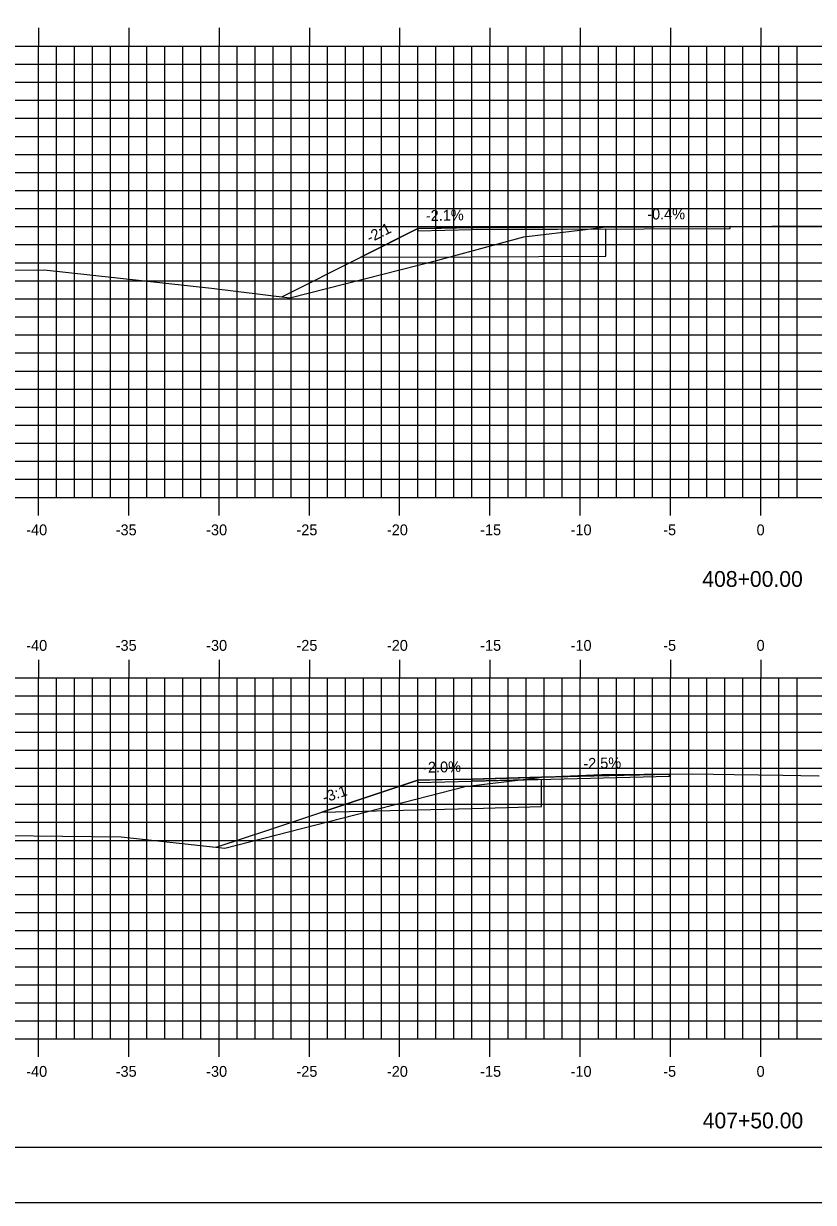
# Model space of a CAD drawing. Extents: x 1168600 to 1177589, y 610178 to 611246.
# Drawn here: x 1171818.2 to 1171862, y 610900.5 to 610965.8 of the extents above; entities that cross this region are included whole.
import ezdxf

# ---------------------------------------------------------------- set-up
doc = ezdxf.new("R2010")
doc.units = 0
for name, color, linetype in [('_Construction', 7, 'Continuous'), ('_Station Equation', 7, 'Continuous'), ('ANNOTATION', 7, 'Continuous'), ('D_Roadway_Edge_TW', 7, 'Continuous'), ('D_Roadway_SubGrade', 7, 'Continuous'), ('D_Slope_Direction', 7, 'Continuous'), ('D_Text_Standard', 7, 'Continuous'), ('H_V ANNOTATION', 7, 'Continuous'), ('MAJOR', 7, 'Continuous'), ('MATCH LINES', 7, 'Continuous'), ('MINOR', 7, 'Continuous')]:
    doc.layers.add(name, color=color, linetype=linetype)

msp = doc.modelspace()

# ---------------------------------------------------------------- linework, layer by layer
at = {"layer": '_Construction'}
msp.add_line((1171784.045, 610903.596), (1171944.045, 610903.596), dxfattribs=at)
msp.add_lwpolyline([(1171775.952, 610900.537), (1171945.952, 610900.537), (1171945.952, 611010.537), (1171775.952, 611010.537)], close=True, dxfattribs=at)
at = {"layer": '_Station Equation'}
for points in [[(1171789.045, 610951.753), (1171796.372, 610951.968), (1171801.834, 610952.028), (1171819.364, 610952.207), (1171828.631, 610951.19), (1171832.957, 610950.654), (1171841.161, 610952.733), (1171845.923, 610954.036), (1171849.324, 610954.437), (1171850.462, 610954.581), (1171859.649, 610954.616), (1171864.065, 610954.632)], [(1171789.045, 610951.753), (1171796.372, 610951.968), (1171801.834, 610952.028), (1171819.364, 610952.207), (1171828.631, 610951.19), (1171832.957, 610950.654), (1171841.161, 610952.733), (1171845.923, 610954.036), (1171849.324, 610954.437), (1171850.462, 610954.581), (1171859.65, 610954.616), (1171864.065, 610954.632)], [(1171789.045, 610920.994), (1171795.223, 610920.863), (1171804.231, 610921.006), (1171823.634, 610920.786), (1171829.366, 610920.156), (1171837.933, 610922.363), (1171842.674, 610923.573), (1171846.665, 610924.058), (1171846.891, 610924.088), (1171848.054, 610924.142), (1171850.234, 610924.245), (1171852.586, 610924.259), (1171855.246, 610924.275), (1171857.567, 610924.244), (1171860.258, 610924.209), (1171862.259, 610924.171)], [(1171789.045, 610920.994), (1171795.223, 610920.863), (1171804.231, 610921.006), (1171823.634, 610920.786), (1171829.366, 610920.156), (1171837.933, 610922.363), (1171842.674, 610923.573), (1171846.664, 610924.058), (1171846.891, 610924.088), (1171848.055, 610924.142), (1171850.234, 610924.245), (1171852.585, 610924.259), (1171855.246, 610924.275), (1171857.567, 610924.244), (1171860.258, 610924.209), (1171862.26, 610924.171)]]:
    msp.add_lwpolyline(points, dxfattribs=at)
at = {"layer": 'D_Roadway_Edge_TW'}
for points in [[(1171857.338, 610954.607), (1171850.462, 610954.581), (1171843.044, 610954.553), (1171840.052, 610954.491), (1171840.052, 610954.366), (1171843.044, 610954.428), (1171857.338, 610954.482)], [(1171857.338, 610954.607), (1171850.462, 610954.581), (1171843.044, 610954.553), (1171840.052, 610954.491), (1171840.052, 610954.366), (1171843.044, 610954.428), (1171857.338, 610954.482)], [(1171857.338, 610954.607), (1171850.462, 610954.581), (1171843.044, 610954.553), (1171843.044, 610954.428), (1171857.338, 610954.482), (1171857.338, 610954.607)], [(1171857.338, 610954.607), (1171850.462, 610954.581), (1171843.044, 610954.553), (1171843.044, 610954.428), (1171857.338, 610954.482), (1171857.338, 610954.607)], [(1171853.976, 610924.268), (1171846.891, 610924.09), (1171843.045, 610923.993), (1171840.05, 610923.932), (1171840.05, 610923.807), (1171843.045, 610923.868), (1171853.976, 610924.143)], [(1171853.976, 610924.268), (1171846.891, 610924.09), (1171843.045, 610923.993), (1171840.05, 610923.932), (1171840.05, 610923.807), (1171843.045, 610923.868), (1171853.976, 610924.143)]]:
    msp.add_lwpolyline(points, close=True, dxfattribs=at)
msp.add_lwpolyline([(1171853.976, 610924.268), (1171846.891, 610924.09), (1171843.045, 610923.993), (1171843.045, 610923.868), (1171853.976, 610924.143), (1171853.976, 610924.268)], dxfattribs=at)
msp.add_lwpolyline([(1171853.976, 610924.268), (1171846.891, 610924.09), (1171843.045, 610923.993), (1171843.045, 610923.868), (1171853.976, 610924.143), (1171853.976, 610924.268)], dxfattribs=at)
at = {"layer": 'D_Roadway_SubGrade'}
for points in [[(1171843.044, 610954.553), (1171840.052, 610954.491), (1171836.893, 610952.905), (1171843.044, 610952.928), (1171850.462, 610952.956), (1171850.462, 610954.456), (1171843.044, 610954.428)], [(1171843.044, 610954.553), (1171840.052, 610954.491), (1171836.893, 610952.905), (1171843.044, 610952.928), (1171850.462, 610952.956), (1171850.462, 610954.456), (1171843.044, 610954.428)], [(1171843.045, 610923.993), (1171840.05, 610923.932), (1171834.733, 610922.16), (1171843.045, 610922.368), (1171846.891, 610922.465), (1171846.891, 610923.965), (1171843.045, 610923.868)], [(1171843.045, 610923.993), (1171840.05, 610923.932), (1171834.733, 610922.16), (1171843.045, 610922.368), (1171846.891, 610922.465), (1171846.891, 610923.965), (1171843.045, 610923.868)]]:
    msp.add_lwpolyline(points, close=True, dxfattribs=at)
at = {"layer": 'D_Slope_Direction'}
for points in [[(1171843.044, 610954.553), (1171840.052, 610954.491)], [(1171843.044, 610954.553), (1171840.052, 610954.491)], [(1171843.045, 610923.993), (1171840.05, 610923.932)], [(1171843.045, 610923.993), (1171840.05, 610923.932)]]:
    msp.add_lwpolyline(points, dxfattribs=at)
at = {"layer": 'D_Text_Standard'}
for points in [[(1171832.518, 610950.709), (1171836.893, 610952.905), (1171838.113, 610953.517), (1171840.052, 610954.491), (1171841.355, 610954.518), (1171843.044, 610954.553), (1171846.989, 610954.568), (1171850.462, 610954.581), (1171853.126, 610954.591), (1171857.338, 610954.607)], [(1171828.883, 610920.21), (1171830.511, 610920.752), (1171831.687, 610921.144), (1171836.671, 610922.806), (1171840.05, 610923.932), (1171841.401, 610923.96), (1171843.045, 610923.993), (1171845.067, 610924.044), (1171846.891, 610924.09), (1171849.816, 610924.163), (1171853.976, 610924.268)]]:
    msp.add_lwpolyline(points, dxfattribs=at)
at = {"layer": 'MAJOR'}
for p, q in [((1171819.045, 610965.598), (1171819.045, 610964.596)), ((1171824.045, 610965.598), (1171824.045, 610964.596)), ((1171829.045, 610965.598), (1171829.045, 610964.596)), ((1171834.045, 610965.598), (1171834.045, 610964.596)), ((1171839.045, 610965.598), (1171839.045, 610964.596)), ((1171844.045, 610965.598), (1171844.045, 610964.596)), ((1171849.045, 610965.598), (1171849.045, 610964.596)), ((1171854.045, 610965.598), (1171854.045, 610964.596)), ((1171859.045, 610965.598), (1171859.045, 610964.596)), ((1171789.045, 610964.596), (1171929.045, 610964.596)), ((1171789.045, 610964.596), (1171929.045, 610964.596)), ((1171819.045, 610939.596), (1171819.045, 610964.596)), ((1171824.045, 610939.596), (1171824.045, 610964.596)), ((1171829.045, 610939.596), (1171829.045, 610964.596)), ((1171834.045, 610939.596), (1171834.045, 610964.596)), ((1171839.045, 610939.596), (1171839.045, 610964.596)), ((1171844.045, 610939.596), (1171844.045, 610964.596)), ((1171849.045, 610939.596), (1171849.045, 610964.596)), ((1171854.045, 610939.596), (1171854.045, 610964.596)), ((1171859.045, 610939.596), (1171859.045, 610964.596)), ((1171789.045, 610959.596), (1171929.045, 610959.596)), ((1171789.045, 610954.596), (1171929.045, 610954.596)), ((1171789.045, 610949.596), (1171929.045, 610949.596)), ((1171789.045, 610944.596), (1171929.045, 610944.596)), ((1171789.045, 610939.596), (1171929.045, 610939.596)), ((1171789.045, 610939.596), (1171929.045, 610939.596)), ((1171819.045, 610938.594), (1171819.045, 610939.596)), ((1171824.045, 610938.594), (1171824.045, 610939.596)), ((1171829.045, 610938.594), (1171829.045, 610939.596)), ((1171834.045, 610938.594), (1171834.045, 610939.596)), ((1171839.045, 610938.594), (1171839.045, 610939.596)), ((1171844.045, 610938.594), (1171844.045, 610939.596)), ((1171849.045, 610938.594), (1171849.045, 610939.596)), ((1171854.045, 610938.594), (1171854.045, 610939.596)), ((1171859.045, 610938.594), (1171859.045, 610939.596)), ((1171819.045, 610930.598), (1171819.045, 610929.596)), ((1171824.045, 610930.598), (1171824.045, 610929.596)), ((1171829.045, 610930.598), (1171829.045, 610929.596)), ((1171834.045, 610930.598), (1171834.045, 610929.596)), ((1171839.045, 610930.598), (1171839.045, 610929.596)), ((1171844.045, 610930.598), (1171844.045, 610929.596)), ((1171849.045, 610930.598), (1171849.045, 610929.596)), ((1171854.045, 610930.598), (1171854.045, 610929.596)), ((1171859.045, 610930.598), (1171859.045, 610929.596)), ((1171789.045, 610929.596), (1171929.045, 610929.596)), ((1171789.045, 610929.596), (1171929.045, 610929.596)), ((1171819.045, 610909.596), (1171819.045, 610929.596)), ((1171824.045, 610909.596), (1171824.045, 610929.596)), ((1171829.045, 610909.596), (1171829.045, 610929.596)), ((1171834.045, 610909.596), (1171834.045, 610929.596)), ((1171839.045, 610909.596), (1171839.045, 610929.596)), ((1171844.045, 610909.596), (1171844.045, 610929.596)), ((1171849.045, 610909.596), (1171849.045, 610929.596)), ((1171854.045, 610909.596), (1171854.045, 610929.596)), ((1171859.045, 610909.596), (1171859.045, 610929.596)), ((1171789.045, 610924.596), (1171929.045, 610924.596)), ((1171789.045, 610919.596), (1171929.045, 610919.596)), ((1171789.045, 610914.596), (1171929.045, 610914.596)), ((1171789.045, 610909.596), (1171929.045, 610909.596)), ((1171789.045, 610909.596), (1171929.045, 610909.596)), ((1171819.045, 610908.594), (1171819.045, 610909.596)), ((1171824.045, 610908.594), (1171824.045, 610909.596)), ((1171829.045, 610908.594), (1171829.045, 610909.596)), ((1171834.045, 610908.594), (1171834.045, 610909.596)), ((1171839.045, 610908.594), (1171839.045, 610909.596)), ((1171844.045, 610908.594), (1171844.045, 610909.596)), ((1171849.045, 610908.594), (1171849.045, 610909.596)), ((1171854.045, 610908.594), (1171854.045, 610909.596)), ((1171859.045, 610908.594), (1171859.045, 610909.596))]:
    msp.add_line(p, q, dxfattribs=at)
at = {"layer": 'MATCH LINES'}
for points in [[(1171843.044, 610954.553), (1171843.044, 610954.428)], [(1171843.044, 610954.553), (1171843.044, 610954.428)], [(1171843.045, 610923.993), (1171843.045, 610923.868)], [(1171843.045, 610923.993), (1171843.045, 610923.868)]]:
    msp.add_lwpolyline(points, dxfattribs=at)
at = {"layer": 'MINOR'}
for p, q in [((1171820.045, 610939.596), (1171820.045, 610964.596)), ((1171821.045, 610939.596), (1171821.045, 610964.596)), ((1171822.045, 610939.596), (1171822.045, 610964.596)), ((1171823.045, 610939.596), (1171823.045, 610964.596)), ((1171825.045, 610939.596), (1171825.045, 610964.596)), ((1171826.045, 610939.596), (1171826.045, 610964.596)), ((1171827.045, 610939.596), (1171827.045, 610964.596)), ((1171828.045, 610939.596), (1171828.045, 610964.596)), ((1171830.045, 610939.596), (1171830.045, 610964.596)), ((1171831.045, 610939.596), (1171831.045, 610964.596)), ((1171832.045, 610939.596), (1171832.045, 610964.596)), ((1171833.045, 610939.596), (1171833.045, 610964.596)), ((1171835.045, 610939.596), (1171835.045, 610964.596)), ((1171836.045, 610939.596), (1171836.045, 610964.596)), ((1171837.045, 610939.596), (1171837.045, 610964.596)), ((1171838.045, 610939.596), (1171838.045, 610964.596)), ((1171840.045, 610939.596), (1171840.045, 610964.596)), ((1171841.045, 610939.596), (1171841.045, 610964.596)), ((1171842.045, 610939.596), (1171842.045, 610964.596)), ((1171843.045, 610939.596), (1171843.045, 610964.596)), ((1171845.045, 610939.596), (1171845.045, 610964.596)), ((1171846.045, 610939.596), (1171846.045, 610964.596)), ((1171847.045, 610939.596), (1171847.045, 610964.596)), ((1171848.045, 610939.596), (1171848.045, 610964.596)), ((1171850.045, 610939.596), (1171850.045, 610964.596)), ((1171851.045, 610939.596), (1171851.045, 610964.596)), ((1171852.045, 610939.596), (1171852.045, 610964.596)), ((1171853.045, 610939.596), (1171853.045, 610964.596)), ((1171855.045, 610939.596), (1171855.045, 610964.596)), ((1171856.045, 610939.596), (1171856.045, 610964.596)), ((1171857.045, 610939.596), (1171857.045, 610964.596)), ((1171858.045, 610939.596), (1171858.045, 610964.596)), ((1171860.045, 610939.596), (1171860.045, 610964.596)), ((1171861.045, 610939.596), (1171861.045, 610964.596)), ((1171789.045, 610963.596), (1171929.045, 610963.596)), ((1171789.045, 610962.596), (1171929.045, 610962.596)), ((1171789.045, 610961.596), (1171929.045, 610961.596)), ((1171789.045, 610960.596), (1171929.045, 610960.596)), ((1171789.045, 610958.596), (1171929.045, 610958.596)), ((1171789.045, 610957.596), (1171929.045, 610957.596)), ((1171789.045, 610956.596), (1171929.045, 610956.596)), ((1171789.045, 610955.596), (1171929.045, 610955.596)), ((1171789.045, 610953.596), (1171929.045, 610953.596)), ((1171789.045, 610952.596), (1171929.045, 610952.596)), ((1171789.045, 610951.596), (1171929.045, 610951.596)), ((1171789.045, 610950.596), (1171929.045, 610950.596)), ((1171789.045, 610948.596), (1171929.045, 610948.596)), ((1171789.045, 610947.596), (1171929.045, 610947.596)), ((1171789.045, 610946.596), (1171929.045, 610946.596)), ((1171789.045, 610945.596), (1171929.045, 610945.596)), ((1171789.045, 610943.596), (1171929.045, 610943.596)), ((1171789.045, 610942.596), (1171929.045, 610942.596)), ((1171789.045, 610941.596), (1171929.045, 610941.596)), ((1171789.045, 610940.596), (1171929.045, 610940.596)), ((1171820.045, 610909.596), (1171820.045, 610929.596)), ((1171821.045, 610909.596), (1171821.045, 610929.596)), ((1171822.045, 610909.596), (1171822.045, 610929.596)), ((1171823.045, 610909.596), (1171823.045, 610929.596)), ((1171825.045, 610909.596), (1171825.045, 610929.596)), ((1171826.045, 610909.596), (1171826.045, 610929.596)), ((1171827.045, 610909.596), (1171827.045, 610929.596)), ((1171828.045, 610909.596), (1171828.045, 610929.596)), ((1171830.045, 610909.596), (1171830.045, 610929.596)), ((1171831.045, 610909.596), (1171831.045, 610929.596)), ((1171832.045, 610909.596), (1171832.045, 610929.596)), ((1171833.045, 610909.596), (1171833.045, 610929.596)), ((1171835.045, 610909.596), (1171835.045, 610929.596)), ((1171836.045, 610909.596), (1171836.045, 610929.596)), ((1171837.045, 610909.596), (1171837.045, 610929.596)), ((1171838.045, 610909.596), (1171838.045, 610929.596)), ((1171840.045, 610909.596), (1171840.045, 610929.596)), ((1171841.045, 610909.596), (1171841.045, 610929.596)), ((1171842.045, 610909.596), (1171842.045, 610929.596)), ((1171843.045, 610909.596), (1171843.045, 610929.596)), ((1171845.045, 610909.596), (1171845.045, 610929.596)), ((1171846.045, 610909.596), (1171846.045, 610929.596)), ((1171847.045, 610909.596), (1171847.045, 610929.596)), ((1171848.045, 610909.596), (1171848.045, 610929.596)), ((1171850.045, 610909.596), (1171850.045, 610929.596)), ((1171851.045, 610909.596), (1171851.045, 610929.596)), ((1171852.045, 610909.596), (1171852.045, 610929.596)), ((1171853.045, 610909.596), (1171853.045, 610929.596)), ((1171855.045, 610909.596), (1171855.045, 610929.596)), ((1171856.045, 610909.596), (1171856.045, 610929.596)), ((1171857.045, 610909.596), (1171857.045, 610929.596)), ((1171858.045, 610909.596), (1171858.045, 610929.596)), ((1171860.045, 610909.596), (1171860.045, 610929.596)), ((1171861.045, 610909.596), (1171861.045, 610929.596)), ((1171789.045, 610928.596), (1171929.045, 610928.596)), ((1171789.045, 610927.596), (1171929.045, 610927.596)), ((1171789.045, 610926.596), (1171929.045, 610926.596)), ((1171789.045, 610925.596), (1171929.045, 610925.596)), ((1171789.045, 610923.596), (1171929.045, 610923.596)), ((1171789.045, 610922.596), (1171929.045, 610922.596)), ((1171789.045, 610921.596), (1171929.045, 610921.596)), ((1171789.045, 610920.596), (1171929.045, 610920.596)), ((1171789.045, 610918.596), (1171929.045, 610918.596)), ((1171789.045, 610917.596), (1171929.045, 610917.596)), ((1171789.045, 610916.596), (1171929.045, 610916.596)), ((1171789.045, 610915.596), (1171929.045, 610915.596)), ((1171789.045, 610913.596), (1171929.045, 610913.596)), ((1171789.045, 610912.596), (1171929.045, 610912.596)), ((1171789.045, 610911.596), (1171929.045, 610911.596)), ((1171789.045, 610910.596), (1171929.045, 610910.596))]:
    msp.add_line(p, q, dxfattribs=at)

# ---------------------------------------------------------------- texts
at = {"layer": 'ANNOTATION'}
for s, rotation, p in [('-2.1%', 1.18418, (1171840.501, 610954.901)), ('-0.4%', 0.22052, (1171852.751, 610954.99)), ('-2:1', 26.66302, (1171837.4, 610953.679)), ('-2.0%', 1.1711, (1171840.35, 610924.338)), ('-2.5%', 1.43561, (1171849.221, 610924.549)), ('-3:1', 18.43495, (1171834.885, 610922.665))]:
    msp.add_text(s, height=0.6, rotation=rotation, dxfattribs=at).set_placement(p)
at = {"layer": 'H_V ANNOTATION'}
for s, height, p in [('-40', 0.6, (1171818.371, 610937.496)), ('-35', 0.6, (1171823.325, 610937.496)), ('-30', 0.6, (1171828.333, 610937.496)), ('-25', 0.6, (1171833.331, 610937.496)), ('-20', 0.6, (1171838.339, 610937.496)), ('-15', 0.6, (1171843.502, 610937.496)), ('-10', 0.6, (1171848.51, 610937.496)), ('-5', 0.6, (1171853.636, 610937.496)), ('0', 0.6, (1171858.804, 610937.496)), ('408+00.00', 0.875, (1171855.799, 610934.639)), ('-40', 0.6, (1171818.371, 610931.096)), ('-35', 0.6, (1171823.325, 610931.096)), ('-30', 0.6, (1171828.333, 610931.096)), ('-25', 0.6, (1171833.331, 610931.096)), ('-20', 0.6, (1171838.339, 610931.096)), ('-15', 0.6, (1171843.502, 610931.096)), ('-10', 0.6, (1171848.51, 610931.096)), ('-5', 0.6, (1171853.636, 610931.096)), ('0', 0.6, (1171858.804, 610931.096)), ('-40', 0.6, (1171818.371, 610907.496)), ('-35', 0.6, (1171823.325, 610907.496)), ('-30', 0.6, (1171828.333, 610907.496)), ('-25', 0.6, (1171833.331, 610907.496)), ('-20', 0.6, (1171838.339, 610907.496)), ('-15', 0.6, (1171843.502, 610907.496)), ('-10', 0.6, (1171848.51, 610907.496)), ('-5', 0.6, (1171853.636, 610907.496)), ('0', 0.6, (1171858.804, 610907.496)), ('407+50.00', 0.875, (1171855.822, 610904.639))]:
    msp.add_text(s, height=height, dxfattribs=at).set_placement(p)

doc.saveas('drawing.dxf')
